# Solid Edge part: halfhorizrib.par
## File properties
Author: harmonj5
Template: ansi part.par
Last saved by: harmonj5
Revision: 10
Application: Solid Edge
Accuracy: 0.990
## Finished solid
Body 1: solid body, 35 faces, 99 edges, 66 vertices.
  Faces by surface: plane 20, cylinder 11, swept 4
  Edges by curve: line 69, circle 22, spline 8
Bounding box of the edges (mm; curved faces can reach further): 85.477 x 3.175 x 17.663, from (-133.9507, -3.175, 34.9527) to (-48.4738, 0, 52.6154).
Cylindrical faces by radius (mm): R3.175 x8, R101.8963 x1, R162.1833 x1, R189.7875 x1
Planar faces by outward normal: +x 7, +y 1, +z 4, -x 3, -y 1, -z 2, oblique 2
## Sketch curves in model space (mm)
line (-133.9507, 0, 42.0053) -> (-133.157, 0, 42.0053)
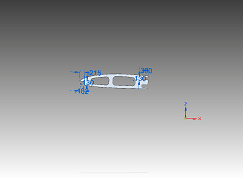
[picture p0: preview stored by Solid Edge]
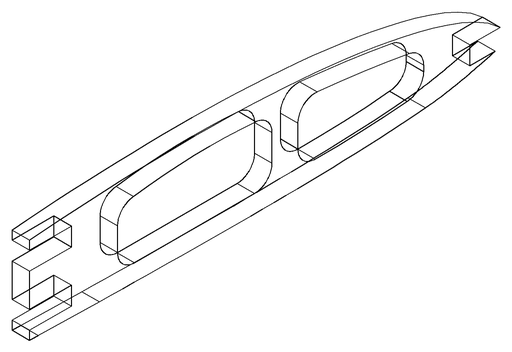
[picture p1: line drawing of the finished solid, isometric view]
